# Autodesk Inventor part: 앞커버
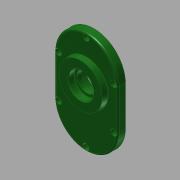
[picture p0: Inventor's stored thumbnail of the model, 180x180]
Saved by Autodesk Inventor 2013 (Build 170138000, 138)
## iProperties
Created: 2016-12
Part Number: 앞커버
Material: 일반
Document SubType Name: Modeling
Designer: mduedu
Density: 1 g/cm^3
Mass: 97.7244 g
Surface Area: 264.104 cm^2
Volume: 97.7244 cm^3
Author: mduedu
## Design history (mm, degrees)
sketch "스케치1"
  geometry: L1 (40, -25)-(40, 25); L2 (-40, 25)-(-40, -25); L3 (-40, -25)-(40, 25); L4 (40, -25)-(-40, 25); A1 r 40 centre (0, 25) between (40, 25) and (-40, 25); A2 r 40 centre (0, -25) between (-40, -25) and (40, -25); 1 further point
  constraints: 8 end point, 4 point on circle, 4 tangent, 2 centre point, 2 midpoint, 1 parallel, 1 vertical
  dimensions: "d0" = 130 dimension on A2 A1; "d2" = 80 distance between parallel lines of L1 L2
extrude "돌출1" new body sketch "스케치1" distance "d3" = 10; taper "d4" = 0 deg
sketch "스케치2"
  geometry: C1 r 21 at (0, 11); 1 further point
  constraints: 1 centre point, 1 vertical alignment
  dimensions: "d5" = 42 diameter of C1; "d7" = 11 distance of C1.centre point (0, 0)
extrude "돌출2" join sketch "스케치2" distance "d8" = 7; taper "d9" = 0 deg
sketch "스케치3"
  geometry: C1 r 15 at (0, -33.1); C2 r 21 at (0, 11) reference; 1 further point
  constraints: 1 centre point, 1 vertical alignment
  dimensions: "d10" = 30 diameter of C1; "d71" = 44.1 distance of C1.centre C2.centre
extrude "돌출3" join sketch "스케치3" distance "d12" = 7; taper "d13" = 0 deg
sketch "스케치4"
  geometry: C1 r 28 at (0, 11); A1 r 21 centre (0, 11) between (8.978, -7.984) and (-8.978, -7.984) reference; 1 further point
  constraints: 1 centre point, 1 coincident
  dimensions: "d14" = 56 diameter of C1
extrude "돌출4" join sketch "스케치4" distance "d15" = 7; taper "d16" = -5 deg
hole "구멍1" diameter "d19" = 35; stored, may be unused: countersink angle "d23" = 90 deg, drill point angle "d25" = 0 deg; dims "d17" = 10, "d18" = 10, "d20" = 6, "d21" = 4, "d22" = 2, "d24" = 10
hole "구멍2" diameter "d28" = 22; stored, may be unused: countersink angle "d32" = 90 deg, drill point angle "d34" = 0 deg; dims "d26" = 10, "d27" = 10, "d29" = 6, "d30" = 4, "d31" = 2, "d33" = 7
hole "구멍3" diameter "d37" = 19; stored, may be unused: countersink angle "d41" = 90 deg, drill point angle "d43" = 0 deg; dims "d35" = 10, "d36" = 10, "d38" = 6, "d39" = 4, "d40" = 2, "d42" = 1
hole "구멍4" diameter "d46" = 32; stored, may be unused: countersink angle "d50" = 90 deg, drill point angle "d52" = 0 deg; dims "d44" = 10, "d45" = 10, "d47" = 6, "d48" = 4, "d49" = 2, "d51" = 8
hole "구멍5" diameter "d55" = 25; stored, may be unused: countersink angle "d59" = 90 deg, drill point angle "d61" = 0 deg; dims "d53" = 10, "d54" = 10, "d56" = 6, "d57" = 4, "d58" = 2, "d60" = 8
fillet "모깎기1" dims "d62" = 0.3
fillet "모깎기2" dims "d63" = 2
chamfer "모따기1" distance "d64" = 1; stored, may be unused: second distance "d65" = 2, angle "d66" = 45 deg
fillet "모깎기4" dims "d68" = 2
fillet "모깎기5" dims "d69" = 0.3
fillet "모깎기6" dims "d70" = 2
sketch "스케치5"
  geometry: L1 (-40, 25)-(-40, -25) reference; L2 (40, -25)-(40, 25) reference; L3 (35, 25)-(35, -25); L4 (-35, -25)-(-35, 25); A1 r 40 centre (0, 25) between (40, 25) and (-40, 25) reference; A2 r 40 centre (0, -25) between (-40, -25) and (40, -25) reference; A3 r 35 centre (0, 25) between (35, 25) and (-35, 25); A4 r 35 centre (0, -25) between (-35, -25) and (35, -25); 2 further points
  constraints: 5 point on circle, 4 end point, 2 centre point, 1 vertical alignment, 3 other
  dimensions: "d72" = 5 distance between parallel lines of L2 L3
sketch "스케치7"
  geometry: 1 further point
hole "구멍7" sketch "스케치7" at (0, 60) diameter "d80" = 4.5; stored, may be unused: countersink angle "d84" = 90 deg, drill point angle "d86" = 0 deg; dims "d81" = 6, "d82" = 8, "d83" = 4.6, "d85" = 8
node "솔리드1"
pattern_linear "직사각형 패턴1"
